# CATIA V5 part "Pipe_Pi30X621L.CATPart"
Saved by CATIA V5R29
Part number: Pipe_Pi30X621L
Source: Unknown
Bounding box of the stored display mesh (mm): x -15 to 15, y -14.97 to 14.97, z -621 to 0
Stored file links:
  C:\가치같이\SmartFactory_BoxErectorConveyor\Boxing(under)\Pipe_Pi30X621L.CATPart
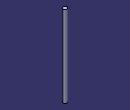
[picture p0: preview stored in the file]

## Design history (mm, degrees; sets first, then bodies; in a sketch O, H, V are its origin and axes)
Body1 (main body)
  Solid1 "PartBody": solid without history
